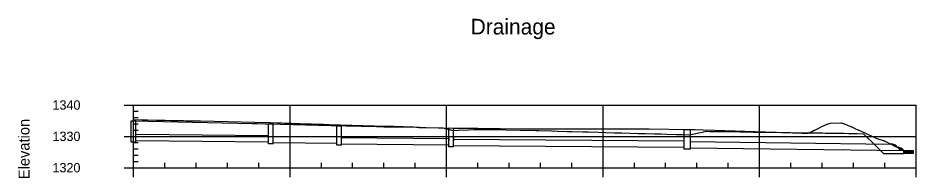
# Model space of a CAD drawing. Extents: x 6712201 to 6713580, y 1869635 to 1871335.
# Drawn here: x 6713004 to 6713578, y 1870485 to 1870588 of the extents above; entities that cross this region are included whole.
import ezdxf

# ---------------------------------------------------------------- set-up
doc = ezdxf.new("R2010")
doc.units = 0
for name, color, linetype in [('56', 7, 'Continuous'), ('58', 7, 'Continuous'), ('C-STRM-PIPE', 7, 'Continuous'), ('C-TOPO-GRAD-E', 7, 'Continuous'), ('INLET', 7, 'Continuous'), ('Proposed Ground', 7, 'Continuous'), ('RSP', 7, 'Continuous')]:
    doc.layers.add(name, color=color, linetype=linetype)

msp = doc.modelspace()

# ---------------------------------------------------------------- linework, layer by layer
at = {"layer": '56'}
for p, q in [((6713071.81, 1870531.99), (6713077.81, 1870531.99)), ((6713071.81, 1870531.99), (6713077.81, 1870531.99)), ((6713077.81, 1870491.99), (6713077.81, 1870531.99)), ((6713077.81, 1870527.99), (6713080.81, 1870527.99)), ((6713077.81, 1870523.99), (6713080.81, 1870523.99)), ((6713077.81, 1870519.99), (6713080.81, 1870519.99)), ((6713077.81, 1870515.99), (6713080.81, 1870515.99)), ((6713071.81, 1870511.99), (6713077.81, 1870511.99)), ((6713077.81, 1870507.99), (6713080.81, 1870507.99)), ((6713077.81, 1870503.99), (6713080.81, 1870503.99)), ((6713077.81, 1870499.99), (6713080.81, 1870499.99)), ((6713071.81, 1870491.99), (6713077.81, 1870491.99)), ((6713077.81, 1870495.99), (6713080.81, 1870495.99)), ((6713077.81, 1870491.99), (6713577.81, 1870491.99)), ((6713077.81, 1870485.99), (6713077.81, 1870491.99)), ((6713097.81, 1870491.99), (6713097.81, 1870494.99)), ((6713117.81, 1870491.99), (6713117.81, 1870494.99)), ((6713137.81, 1870491.99), (6713137.81, 1870494.99)), ((6713157.81, 1870491.99), (6713157.81, 1870494.99)), ((6713177.81, 1870485.99), (6713177.81, 1870491.99)), ((6713197.81, 1870491.99), (6713197.81, 1870494.99)), ((6713217.81, 1870491.99), (6713217.81, 1870494.99)), ((6713237.81, 1870491.99), (6713237.81, 1870494.99)), ((6713257.81, 1870491.99), (6713257.81, 1870494.99)), ((6713277.81, 1870485.99), (6713277.81, 1870491.99)), ((6713297.81, 1870491.99), (6713297.81, 1870494.99)), ((6713317.81, 1870491.99), (6713317.81, 1870494.99)), ((6713337.81, 1870491.99), (6713337.81, 1870494.99)), ((6713357.81, 1870491.99), (6713357.81, 1870494.99)), ((6713377.81, 1870485.99), (6713377.81, 1870491.99)), ((6713397.81, 1870491.99), (6713397.81, 1870494.99)), ((6713417.81, 1870491.99), (6713417.81, 1870494.99)), ((6713437.81, 1870491.99), (6713437.81, 1870494.99)), ((6713457.81, 1870491.99), (6713457.81, 1870494.99)), ((6713477.81, 1870485.99), (6713477.81, 1870491.99)), ((6713497.81, 1870491.99), (6713497.81, 1870494.99)), ((6713517.81, 1870491.99), (6713517.81, 1870494.99)), ((6713537.81, 1870491.99), (6713537.81, 1870494.99)), ((6713557.81, 1870491.99), (6713557.81, 1870494.99)), ((6713577.81, 1870485.99), (6713577.81, 1870491.99))]:
    msp.add_line(p, q, dxfattribs=at)
at = {"layer": '58'}
for p, q in [((6713077.81, 1870531.99), (6713577.81, 1870531.99)), ((6713077.81, 1870531.99), (6713577.81, 1870531.99)), ((6713177.81, 1870491.99), (6713177.81, 1870531.99)), ((6713277.81, 1870491.99), (6713277.81, 1870531.99)), ((6713377.81, 1870491.99), (6713377.81, 1870531.99)), ((6713477.81, 1870491.99), (6713477.81, 1870531.99)), ((6713577.81, 1870491.99), (6713577.81, 1870531.99)), ((6713077.81, 1870511.99), (6713577.81, 1870511.99))]:
    msp.add_line(p, q, dxfattribs=at)
at = {"layer": 'C-STRM-PIPE'}
for p, q in [((6713079.31, 1870513.35), (6713164.03, 1870512.51)), ((6713079.31, 1870509.35), (6713164.03, 1870508.51)), ((6713167.07, 1870512.11), (6713207.82, 1870511.71)), ((6713210.78, 1870511.31), (6713279.34, 1870510.63)), ((6713282.34, 1870510.23), (6713429.53, 1870509.15)), ((6713167.03, 1870508.11), (6713207.78, 1870507.71)), ((6713210.78, 1870507.31), (6713279.34, 1870506.63)), ((6713282.34, 1870506.23), (6713429.53, 1870505.15)), ((6713433.53, 1870508.75), (6713561.72, 1870507.09)), ((6713433.53, 1870504.75), (6713570.04, 1870502.98)), ((6713561.72, 1870507.09), (6713561.72, 1870507.09)), ((6713565.87, 1870505.04), (6713565.87, 1870505.04)), ((6713570.01, 1870502.99), (6713570.01, 1870502.99))]:
    msp.add_line(p, q, dxfattribs=at)
for centre, radius, start, end in [((6713561.46, 1870501.33), 5.76, 40.07546, 87.34564), ((6713565.29, 1870498.62), 6.44, 42.53399, 84.88573), ((6713571.05, 1870510.27), 7.36, 225.28981, 262.12978)]:
    msp.add_arc(centre, radius, start, end, dxfattribs=at)
at = {"layer": 'C-TOPO-GRAD-E'}
msp.add_lwpolyline([(6713077.81, 1870522.68), (6713083.28, 1870522.58), (6713083.99, 1870522.56), (6713084.78, 1870522.54), (6713085.66, 1870522.52), (6713086.64, 1870522.5), (6713092.42, 1870522.39), (6713093.32, 1870522.37), (6713094.31, 1870522.35), (6713095.42, 1870522.32), (6713096.65, 1870522.3), (6713098.04, 1870522.27), (6713101.53, 1870522.2), (6713102.7, 1870522.18), (6713104.02, 1870522.15), (6713105.51, 1870522.11), (6713107.18, 1870522.08), (6713109.08, 1870522.04), (6713109.75, 1870522.03), (6713111.26, 1870521.99), (6713111.31, 1870521.99), (6713114.88, 1870521.92), (6713118.28, 1870521.86), (6713118.63, 1870521.85), (6713119.03, 1870521.84), (6713119.49, 1870521.82), (6713120.03, 1870521.81), (6713120.68, 1870521.79), (6713164.01, 1870520.82), (6713165.33, 1870520.77), (6713170.02, 1870520.64), (6713171.19, 1870520.6), (6713172.51, 1870520.55), (6713174.01, 1870520.49), (6713175.71, 1870520.43), (6713178.78, 1870520.34), (6713180.24, 1870520.28), (6713181.92, 1870520.22), (6713183.88, 1870520.14), (6713186.2, 1870520.05), (6713186.67, 1870520.04), (6713187.67, 1870519.99), (6713189.19, 1870519.95), (6713191.58, 1870519.89), (6713193.59, 1870519.83), (6713196.5, 1870519.74), (6713198.98, 1870519.67), (6713201.08, 1870519.61), (6713202.9, 1870519.56), (6713238.8, 1870518.57), (6713244.21, 1870518.39), (6713250.08, 1870518.19), (6713255.91, 1870517.99), (6713256.69, 1870517.97), (6713264.51, 1870517.74), (6713274.32, 1870517.44), (6713275.45, 1870517.4), (6713275.45, 1870517.4), (6713275.47, 1870517.4), (6713280.42, 1870516.06), (6713281.9, 1870515.66), (6713285.33, 1870515.88), (6713285.34, 1870515.88), (6713291.76, 1870516.13), (6713295.24, 1870516.26), (6713295.25, 1870516.26), (6713303.48, 1870516.37), (6713305.06, 1870516.39), (6713305.07, 1870516.39), (6713306.39, 1870516.38), (6713314.88, 1870516.28), (6713314.88, 1870516.28), (6713315.98, 1870516.25), (6713324.81, 1870516), (6713324.83, 1870516), (6713324.83, 1870516), (6713326.27, 1870515.96), (6713334.83, 1870515.72), (6713336.67, 1870515.67), (6713344.84, 1870515.44), (6713346.06, 1870515.4), (6713346.06, 1870515.41), (6713348.44, 1870515.34), (6713354.84, 1870515.16), (6713357.88, 1870515.08), (6713364.84, 1870514.89), (6713368.61, 1870514.78), (6713374.84, 1870514.61), (6713379.24, 1870514.48), (6713384.84, 1870514.33), (6713389.81, 1870514.19), (6713394.84, 1870514.05), (6713400.31, 1870513.89), (6713404.84, 1870513.77), (6713410.76, 1870513.6), (6713414.84, 1870513.49), (6713418.62, 1870513.38), (6713424.84, 1870513.21), (6713428.45, 1870513.11), (6713432.61, 1870512.99), (6713435.07, 1870513.46), (6713444.23, 1870515.19), (6713446.11, 1870515.16), (6713456.54, 1870514.99), (6713465.74, 1870514.83), (6713473.7, 1870514.69), (6713491.89, 1870514.38), (6713493.47, 1870514.37), (6713493.68, 1870514.36), (6713495.28, 1870514.35), (6713495.48, 1870514.35), (6713497.1, 1870514.34), (6713497.3, 1870514.34), (6713498.93, 1870514.33), (6713500.6, 1870514.32), (6713500.78, 1870514.31), (6713502.47, 1870514.3), (6713502.65, 1870514.3), (6713504.36, 1870514.28), (6713504.53, 1870514.28), (6713506.26, 1870514.27), (6713508.03, 1870514.25), (6713508.18, 1870514.25), (6713509.98, 1870514.23), (6713510.11, 1870514.23), (6713511.94, 1870514.21), (6713512.07, 1870514.21), (6713513.92, 1870514.19), (6713514.04, 1870514.19), (6713515.92, 1870514.16), (6713517.85, 1870514.14), (6713517.94, 1870514.14), (6713519.9, 1870514.12), (6713519.98, 1870514.11), (6713521.98, 1870514.09), (6713522.04, 1870514.09), (6713524.07, 1870514.06), (6713526.17, 1870514.03), (6713526.19, 1870514.03), (6713528.32, 1870514), (6713528.33, 1870514), (6713528.62, 1870513.99), (6713531.85, 1870513.92), (6713534.67, 1870513.86), (6713535.24, 1870513.84), (6713537.39, 1870513.79), (6713539, 1870513.75), (6713540.24, 1870513.72), (6713544.27, 1870513.62), (6713552.46, 1870505.49), (6713553.19, 1870504.77), (6713555.24, 1870502.74), (6713557, 1870500.99), (6713570.01, 1870500.99)], dxfattribs=at)
at = {"layer": 'INLET'}
for p, q in [((6713076.31, 1870508.35), (6713076.31, 1870521.94)), ((6713076.31, 1870521.94), (6713079.31, 1870521.88)), ((6713079.31, 1870508.35), (6713079.31, 1870521.88)), ((6713164.03, 1870507.11), (6713164.03, 1870519.99)), ((6713164.03, 1870519.99), (6713167.03, 1870519.89)), ((6713167.03, 1870507.11), (6713167.03, 1870519.89)), ((6713207.78, 1870506.31), (6713207.78, 1870518.76)), ((6713207.78, 1870518.76), (6713210.78, 1870518.71)), ((6713210.78, 1870506.31), (6713210.78, 1870518.71)), ((6713279.34, 1870505.23), (6713279.34, 1870517.34)), ((6713279.34, 1870517.34), (6713282.34, 1870517.29)), ((6713282.34, 1870505.23), (6713282.34, 1870517.29)), ((6713429.53, 1870516.36), (6713429.53, 1870503.75)), ((6713429.53, 1870516.36), (6713433.53, 1870516.34)), ((6713433.53, 1870516.34), (6713433.53, 1870503.75)), ((6713279.34, 1870511.99), (6713279.34, 1870509.43)), ((6713282.34, 1870511.99), (6713282.34, 1870509.03)), ((6713079.31, 1870508.35), (6713076.31, 1870508.35)), ((6713167.03, 1870507.11), (6713164.03, 1870507.11)), ((6713210.78, 1870506.31), (6713207.78, 1870506.31)), ((6713282.34, 1870505.23), (6713279.34, 1870505.23)), ((6713433.53, 1870503.75), (6713429.53, 1870503.75))]:
    msp.add_line(p, q, dxfattribs=at)
at = {"layer": 'Proposed Ground'}
msp.add_lwpolyline([(6713077.81, 1870521.91), (6713134.34, 1870520.64), (6713134.43, 1870520.64), (6713134.52, 1870520.64), (6713134.63, 1870520.63), (6713134.74, 1870520.63), (6713134.86, 1870520.63), (6713134.98, 1870520.63), (6713135.11, 1870520.63), (6713153.74, 1870520.18), (6713153.79, 1870520.18), (6713153.83, 1870520.18), (6713153.88, 1870520.18), (6713156.86, 1870520.12), (6713162.07, 1870519.99), (6713163.32, 1870519.99), (6713204.16, 1870518.86), (6713233.03, 1870518.19), (6713237.76, 1870517.99), (6713243.2, 1870517.99), (6713246.13, 1870517.99), (6713248, 1870517.99), (6713248.37, 1870517.99), (6713248.73, 1870517.99), (6713249.07, 1870517.99), (6713249.41, 1870517.99), (6713249.73, 1870517.99), (6713258.6, 1870517.75), (6713259.85, 1870517.72), (6713261.1, 1870517.69), (6713262.33, 1870517.66), (6713263.54, 1870517.64), (6713281.9, 1870517.29), (6713297.87, 1870517.29), (6713326.85, 1870516.72), (6713337.08, 1870516.72), (6713346.72, 1870516.71), (6713362.86, 1870516.7), (6713379.03, 1870516.69), (6713407.23, 1870516.71), (6713432.61, 1870516.32), (6713436.71, 1870516.43), (6713441.71, 1870516.25), (6713448.94, 1870515.99), (6713488.4, 1870514.59), (6713505.01, 1870513.99), (6713508.96, 1870513.99), (6713509.8, 1870514.4), (6713511.62, 1870515.29), (6713512.76, 1870515.84), (6713513.08, 1870515.99), (6713515.32, 1870517.08), (6713517.21, 1870517.99), (6713517.69, 1870518.23), (6713519.16, 1870518.93), (6713521.36, 1870519.99), (6713521.65, 1870520.08), (6713521.66, 1870520.08), (6713521.67, 1870520.08), (6713521.69, 1870520.08), (6713523.06, 1870520.45), (6713529.79, 1870520.53), (6713529.86, 1870520.53), (6713530.46, 1870520.38), (6713530.51, 1870520.38), (6713530.56, 1870520.38), (6713531.26, 1870520.19), (6713531.28, 1870520.19), (6713531.97, 1870519.99), (6713532.18, 1870519.91), (6713532.28, 1870519.86), (6713533.55, 1870519.32), (6713534.42, 1870518.94), (6713535.11, 1870518.64), (6713536.59, 1870517.99), (6713536.89, 1870517.86), (6713537.12, 1870517.76), (6713538.74, 1870517.04), (6713540.67, 1870516.19), (6713540.86, 1870516.1), (6713541.11, 1870515.99), (6713542.71, 1870515.28), (6713544.08, 1870514.66), (6713544.72, 1870514.37), (6713545.55, 1870513.99), (6713547.16, 1870513.26), (6713548.69, 1870512.56), (6713549.35, 1870512.25), (6713549.92, 1870511.99), (6713550.14, 1870511.89), (6713550.71, 1870511.59), (6713551.12, 1870511.38), (6713551.42, 1870511.22), (6713551.64, 1870511.09), (6713554.6, 1870509.99), (6713556.98, 1870509.43), (6713557.08, 1870509.37), (6713557.21, 1870509.3), (6713557.39, 1870509.21), (6713557.65, 1870509.09), (6713557.88, 1870508.99), (6713558.4, 1870508.74), (6713559.89, 1870507.99), (6713559.98, 1870507.95), (6713560.1, 1870507.89), (6713562.47, 1870506.72), (6713563.93, 1870505.99), (6713564.78, 1870505.58), (6713565.73, 1870505.1), (6713566.99, 1870504.49), (6713567.98, 1870503.99), (6713568.69, 1870503.64), (6713570.01, 1870502.99)], dxfattribs=at)
at = {"layer": 'RSP'}
msp.add_lwpolyline([(6713570.04, 1870502.98), (6713576.04, 1870502.98), (6713576.04, 1870500.98), (6713570.04, 1870500.98)], close=True, dxfattribs=at)
for centre, major_axis, ratio, start_param, end_param in [((6713569.83, 1870502.93), (-0.047, -0.362), 0.928532, 0.790319, 1.814497), ((6713570.31, 1870502.34), (-0.233, -0.403), 0.447584, 6.039019, 11.492917), ((6713569.7, 1870501.44), (0.453, 0.053), 0.797741, 5.461125, 6.91809), ((6713570.04, 1870500.52), (-0.193, -0.461), 0.798412, 3.101973, 3.614091), ((6713570.85, 1870501.25), (-0.321, -0.487), 0.536537, 1.359675, 5.604367), ((6713571.29, 1870502.99), (0.163, -0.42), 0.813117, 4.433256, 7.520588), ((6713571.4, 1870500.66), (-0.047, -0.362), 0.928532, 2.764022, 3.757647), ((6713572.07, 1870502.95), (-0.305, -0.305), 0.447584, 5.050786, 8.358138), ((6713572.15, 1870500.41), (0.064, -0.618), 0.416263, 2.702579, 3.494266), ((6713572.72, 1870501.13), (0.136, -0.662), 0.62296, 1.216181, 4.811312), ((6713572.77, 1870503.09), (-0.204, -0.478), 0.614268, 5.190604, 7.888599), ((6713573.61, 1870501.29), (-0.193, -0.461), 0.798412, 1.18552, 5.741492), ((6713574.06, 1870500.46), (0.064, -0.618), 0.416263, 2.517506, 3.679339), ((6713574.36, 1870503.17), (-0.204, -0.478), 0.614268, 5.359051, 7.720151), ((6713574.73, 1870501.1), (0.152, -0.735), 0.62296, 1.279231, 4.748262), ((6713575.2, 1870503.17), (0.163, -0.42), 0.813117, 4.850288, 7.103556), ((6713575.6, 1870500.69), (-0.047, -0.362), 0.928532, 2.626455, 3.895214), ((6713576.1, 1870502.72), (-0.431, 0), 0.447584, 4.844469, 7.722421), ((6713576.15, 1870501.29), (0.051, -0.496), 0.416263, 3.455257, 5.342586)]:
    msp.add_ellipse(centre, major_axis=major_axis, ratio=ratio, start_param=start_param, end_param=end_param, dxfattribs=at)
for centre, major_axis, ratio in [((6713570.95, 1870502.24), (-0.037, -0.286), 0.928532), ((6713571.66, 1870501.41), (-0.154, -0.37), 0.798412), ((6713572.16, 1870502.31), (-0.144, -0.337), 0.614268), ((6713572.85, 1870502.23), (-0.04, -0.312), 0.928532), ((6713573.65, 1870502.46), (-0.187, -0.448), 0.798412), ((6713574.65, 1870502.39), (-0.259, -0.448), 0.447584), ((6713575.55, 1870502.23), (0.367, -0.298), 0.416263), ((6713575.55, 1870501.47), (-0.216, -0.373), 0.447584)]:
    msp.add_ellipse(centre, major_axis=major_axis, ratio=ratio, dxfattribs=at)

# ---------------------------------------------------------------- texts
at = {"layer": '56'}
for s, height, p in [('Drainage', 10, (6713293.21, 1870576.99)), ('1340', 6, (6713026.01, 1870528.99)), ('1340', 6, (6713026.01, 1870528.99)), ('1330', 6, (6713026.01, 1870508.99)), ('1320', 6, (6713026.01, 1870488.99)), ('-', 0.0001, (6713077.81, 1870491.99))]:
    msp.add_text(s, height=height, dxfattribs=at).set_placement(p)
msp.add_text('Elevation', height=7, rotation=90, dxfattribs=at).set_placement((6713011.31, 1870484.63))

doc.saveas('drawing.dxf')
